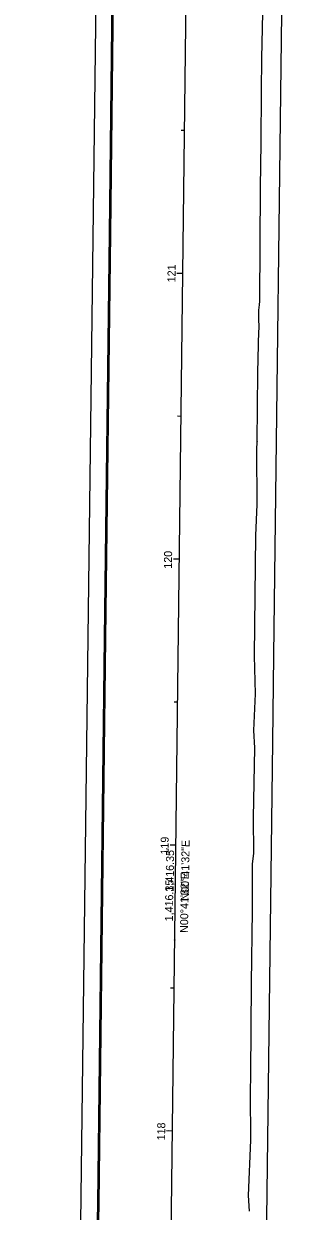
# Model space of a CAD drawing. Extents: x 1652464 to 1652601, y 605963 to 608618.
# Drawn here: x 1652507.3 to 1652601.5, y 607787.6 to 608203 of the extents above; entities that cross this region are included whole.
import ezdxf

# ---------------------------------------------------------------- set-up
doc = ezdxf.new("R2010")
doc.units = 0
for name, color, linetype in [('BD_X_Building', 7, 'Continuous'), ('BR_X_SV_Abut', 7, 'Continuous'), ('DR_X_Erosion_Control', 7, 'Continuous'), ('GE_X_Cells', 7, 'Continuous'), ('PV_X_Curb', 7, 'Continuous'), ('PV_X_Steps', 7, 'Continuous'), ('PV_X_Walk', 7, 'Continuous'), ('SV_P_Mon_Cells_Set', 7, 'Continuous'), ('SV_X_Control_Cells_Found', 7, 'Continuous'), ('SV_X_Mon_Cells_Found', 7, 'Continuous'), ('UT_X_Water_Cells', 7, 'Continuous'), ('VG_X_Cells', 7, 'Continuous'), ('VG_X_Shrub_Line_Lt', 7, 'Continuous')]:
    doc.layers.add(name, color=color, linetype=linetype)

msp = doc.modelspace()

# ---------------------------------------------------------------- linework, layer by layer
at = {"layer": 'BD_X_Building'}
msp.add_lwpolyline([(1652507.27, 606201.32), (1652514.36, 606755.06), (1652515.19, 606820.32), (1652516.55, 606927.44), (1652537.47, 608602.59)], dxfattribs=at)
at = {"layer": 'GE_X_Cells'}
for p, q in [((1652537.74, 608129.62), (1652539.44, 608285.59)), ((1652590.51, 608190.93), (1652590.92, 608212.2)), ((1652590.51, 608190.93), (1652590.92, 608212.2)), ((1652590.51, 608190.93), (1652590.92, 608212.2)), ((1652590.51, 608190.93), (1652590.92, 608212.2)), ((1652590.51, 608190.93), (1652590.92, 608212.2)), ((1652590.51, 608190.93), (1652590.92, 608212.2)), ((1652590.32, 608179.32), (1652590.51, 608190.93)), ((1652590.32, 608179.32), (1652590.51, 608190.93)), ((1652590.32, 608179.32), (1652590.51, 608190.93)), ((1652590.32, 608179.32), (1652590.51, 608190.93)), ((1652590.32, 608179.32), (1652590.51, 608190.93)), ((1652590.32, 608179.32), (1652590.51, 608190.93)), ((1652590.21, 608161.26), (1652590.32, 608179.32)), ((1652590.21, 608161.26), (1652590.32, 608179.32)), ((1652590.21, 608161.26), (1652590.32, 608179.32)), ((1652590.21, 608161.26), (1652590.32, 608179.32)), ((1652590.21, 608161.26), (1652590.32, 608179.32)), ((1652590.21, 608161.26), (1652590.32, 608179.32)), ((1652590.01, 608145.63), (1652590.21, 608161.26)), ((1652590.01, 608145.63), (1652590.21, 608161.26)), ((1652590.01, 608145.63), (1652590.21, 608161.26)), ((1652590.01, 608145.63), (1652590.21, 608161.26)), ((1652590.01, 608145.63), (1652590.21, 608161.26)), ((1652590.01, 608145.63), (1652590.21, 608161.26)), ((1652589.77, 608105.94), (1652590.01, 608145.63)), ((1652589.77, 608105.94), (1652590.01, 608145.63)), ((1652589.77, 608105.94), (1652590.01, 608145.63)), ((1652589.77, 608105.94), (1652590.01, 608145.63)), ((1652589.77, 608105.94), (1652590.01, 608145.63)), ((1652589.77, 608105.94), (1652590.01, 608145.63)), ((1652535.98, 607988.06), (1652537.74, 608129.62)), ((1652589.47, 608102.82), (1652589.65, 608104.61)), ((1652589.47, 608102.82), (1652589.65, 608104.61)), ((1652589.47, 608102.82), (1652589.65, 608104.61)), ((1652589.47, 608102.82), (1652589.65, 608104.61)), ((1652589.47, 608102.82), (1652589.65, 608104.61)), ((1652589.47, 608102.82), (1652589.65, 608104.61)), ((1652589.65, 608104.61), (1652589.77, 608105.94)), ((1652589.65, 608104.61), (1652589.77, 608105.94)), ((1652589.65, 608104.61), (1652589.77, 608105.94)), ((1652589.65, 608104.61), (1652589.77, 608105.94)), ((1652589.65, 608104.61), (1652589.77, 608105.94)), ((1652589.65, 608104.61), (1652589.77, 608105.94)), ((1652589.42, 608100.41), (1652589.47, 608102.82)), ((1652589.42, 608100.41), (1652589.47, 608102.82)), ((1652589.42, 608100.41), (1652589.47, 608102.82)), ((1652589.42, 608100.41), (1652589.47, 608102.82)), ((1652589.42, 608100.41), (1652589.47, 608102.82)), ((1652589.42, 608100.41), (1652589.47, 608102.82)), ((1652589.58, 608096.16), (1652589.42, 608100.41)), ((1652589.58, 608096.16), (1652589.42, 608100.41)), ((1652589.58, 608096.16), (1652589.42, 608100.41)), ((1652589.58, 608096.16), (1652589.42, 608100.41)), ((1652589.58, 608096.16), (1652589.42, 608100.41)), ((1652589.58, 608096.16), (1652589.42, 608100.41)), ((1652589.11, 608080.96), (1652589.49, 608095.57)), ((1652589.11, 608080.96), (1652589.49, 608095.57)), ((1652589.11, 608080.96), (1652589.49, 608095.57)), ((1652589.11, 608080.96), (1652589.49, 608095.57)), ((1652589.11, 608080.96), (1652589.49, 608095.57)), ((1652589.11, 608080.96), (1652589.49, 608095.57)), ((1652589.49, 608095.57), (1652589.58, 608096.16)), ((1652589.49, 608095.57), (1652589.58, 608096.16)), ((1652589.49, 608095.57), (1652589.58, 608096.16)), ((1652589.49, 608095.57), (1652589.58, 608096.16)), ((1652589.49, 608095.57), (1652589.58, 608096.16)), ((1652589.49, 608095.57), (1652589.58, 608096.16)), ((1652588.88, 608056.71), (1652589.11, 608080.96)), ((1652588.88, 608056.71), (1652589.11, 608080.96)), ((1652588.88, 608056.71), (1652589.11, 608080.96)), ((1652588.88, 608056.71), (1652589.11, 608080.96)), ((1652588.88, 608056.71), (1652589.11, 608080.96)), ((1652588.88, 608056.71), (1652589.11, 608080.96)), ((1652588.7, 608053.93), (1652588.9, 608056.78)), ((1652588.7, 608053.93), (1652588.9, 608056.78)), ((1652588.7, 608053.93), (1652588.9, 608056.78)), ((1652588.7, 608053.93), (1652588.9, 608056.78)), ((1652588.7, 608053.93), (1652588.9, 608056.78)), ((1652588.7, 608053.93), (1652588.9, 608056.78)), ((1652588.83, 608034.79), (1652588.7, 608053.93)), ((1652588.83, 608034.79), (1652588.7, 608053.93)), ((1652588.83, 608034.79), (1652588.7, 608053.93)), ((1652588.83, 608034.79), (1652588.7, 608053.93)), ((1652588.83, 608034.79), (1652588.7, 608053.93)), ((1652588.83, 608034.79), (1652588.7, 608053.93)), ((1652588.9, 608056.78), (1652588.88, 608056.71)), ((1652588.9, 608056.78), (1652588.88, 608056.71)), ((1652588.9, 608056.78), (1652588.88, 608056.71)), ((1652588.9, 608056.78), (1652588.88, 608056.71)), ((1652588.9, 608056.78), (1652588.88, 608056.71)), ((1652588.9, 608056.78), (1652588.88, 608056.71)), ((1652588.43, 608023.95), (1652588.83, 608034.79)), ((1652588.43, 608023.95), (1652588.83, 608034.79)), ((1652588.43, 608023.95), (1652588.83, 608034.79)), ((1652588.43, 608023.95), (1652588.83, 608034.79)), ((1652588.43, 608023.95), (1652588.83, 608034.79)), ((1652588.43, 608023.95), (1652588.83, 608034.79)), ((1652587.91, 607981.83), (1652588.43, 608023.95)), ((1652587.91, 607981.83), (1652588.43, 608023.95)), ((1652587.91, 607981.83), (1652588.43, 608023.95)), ((1652587.91, 607981.83), (1652588.43, 608023.95)), ((1652587.91, 607981.83), (1652588.43, 608023.95)), ((1652587.91, 607981.83), (1652588.43, 608023.95)), ((1652533.61, 607790.33), (1652535.98, 607988.06)), ((1652588.27, 607968.59), (1652587.91, 607981.83)), ((1652588.27, 607968.59), (1652587.91, 607981.83)), ((1652588.27, 607968.59), (1652587.91, 607981.83)), ((1652588.27, 607968.59), (1652587.91, 607981.83)), ((1652588.27, 607968.59), (1652587.91, 607981.83)), ((1652588.27, 607968.59), (1652587.91, 607981.83)), ((1652587.69, 607955.8), (1652588.27, 607968.59)), ((1652587.69, 607955.8), (1652588.27, 607968.59)), ((1652587.69, 607955.8), (1652588.27, 607968.59)), ((1652587.69, 607955.8), (1652588.27, 607968.59)), ((1652587.69, 607955.8), (1652588.27, 607968.59)), ((1652587.69, 607955.8), (1652588.27, 607968.59)), ((1652588.03, 607949.63), (1652587.69, 607955.8)), ((1652588.03, 607949.63), (1652587.69, 607955.8)), ((1652588.03, 607949.63), (1652587.69, 607955.8)), ((1652588.03, 607949.63), (1652587.69, 607955.8)), ((1652588.03, 607949.63), (1652587.69, 607955.8)), ((1652588.03, 607949.63), (1652587.69, 607955.8)), ((1652587.55, 607925.17), (1652588.03, 607949.63)), ((1652587.55, 607925.17), (1652588.03, 607949.63)), ((1652587.55, 607925.17), (1652588.03, 607949.63)), ((1652587.55, 607925.17), (1652588.03, 607949.63)), ((1652587.55, 607925.17), (1652588.03, 607949.63)), ((1652587.55, 607925.17), (1652588.03, 607949.63)), ((1652587.75, 607912.8), (1652587.55, 607925.17)), ((1652587.75, 607912.8), (1652587.55, 607925.17)), ((1652587.75, 607912.8), (1652587.55, 607925.17)), ((1652587.75, 607912.8), (1652587.55, 607925.17)), ((1652587.75, 607912.8), (1652587.55, 607925.17)), ((1652587.75, 607912.8), (1652587.55, 607925.17)), ((1652587.25, 607908.98), (1652587.75, 607912.8)), ((1652587.25, 607908.98), (1652587.75, 607912.8)), ((1652587.25, 607908.98), (1652587.75, 607912.8)), ((1652587.25, 607908.98), (1652587.75, 607912.8)), ((1652587.25, 607908.98), (1652587.75, 607912.8)), ((1652587.25, 607908.98), (1652587.75, 607912.8)), ((1652587.28, 607892.75), (1652587.25, 607908.98)), ((1652587.28, 607892.75), (1652587.25, 607908.98)), ((1652587.28, 607892.75), (1652587.25, 607908.98)), ((1652587.28, 607892.75), (1652587.25, 607908.98)), ((1652587.28, 607892.75), (1652587.25, 607908.98)), ((1652587.28, 607892.75), (1652587.25, 607908.98)), ((1652586.86, 607867.34), (1652587.28, 607892.75)), ((1652586.86, 607867.34), (1652587.28, 607892.75)), ((1652586.86, 607867.34), (1652587.28, 607892.75)), ((1652586.86, 607867.34), (1652587.28, 607892.75)), ((1652586.86, 607867.34), (1652587.28, 607892.75)), ((1652586.86, 607867.34), (1652587.28, 607892.75)), ((1652586.66, 607835.54), (1652586.86, 607867.34)), ((1652586.66, 607835.54), (1652586.86, 607867.34)), ((1652586.66, 607835.54), (1652586.86, 607867.34)), ((1652586.66, 607835.54), (1652586.86, 607867.34)), ((1652586.66, 607835.54), (1652586.86, 607867.34)), ((1652586.66, 607835.54), (1652586.86, 607867.34)), ((1652586.53, 607829.02), (1652586.66, 607835.54)), ((1652586.53, 607829.02), (1652586.66, 607835.54)), ((1652586.53, 607829.02), (1652586.66, 607835.54)), ((1652586.53, 607829.02), (1652586.66, 607835.54)), ((1652586.53, 607829.02), (1652586.66, 607835.54)), ((1652586.53, 607829.02), (1652586.66, 607835.54)), ((1652586.61, 607812.41), (1652586.53, 607829.02)), ((1652586.61, 607812.41), (1652586.53, 607829.02)), ((1652586.61, 607812.41), (1652586.53, 607829.02)), ((1652586.61, 607812.41), (1652586.53, 607829.02)), ((1652586.61, 607812.41), (1652586.53, 607829.02)), ((1652586.61, 607812.41), (1652586.53, 607829.02)), ((1652585.81, 607793.1), (1652586.61, 607812.41)), ((1652585.81, 607793.1), (1652586.61, 607812.41)), ((1652585.81, 607793.1), (1652586.61, 607812.41)), ((1652585.81, 607793.1), (1652586.61, 607812.41)), ((1652585.81, 607793.1), (1652586.61, 607812.41)), ((1652585.81, 607793.1), (1652586.61, 607812.41)), ((1652586.21, 607787.58), (1652585.81, 607793.1)), ((1652586.21, 607787.58), (1652585.81, 607793.1)), ((1652586.21, 607787.58), (1652585.81, 607793.1)), ((1652586.21, 607787.58), (1652585.81, 607793.1)), ((1652586.21, 607787.58), (1652585.81, 607793.1)), ((1652586.21, 607787.58), (1652585.81, 607793.1)), ((1652531.98, 607668.47), (1652533.61, 607790.33))]:
    msp.add_line(p, q, dxfattribs=at)
at = {"layer": 'PV_X_Curb'}
msp.add_line((1652551.76, 607199.34), (1652568.87, 608615.58), dxfattribs=at)
at = {"layer": 'PV_X_Steps'}
msp.add_lwpolyline([(1652570.42, 606048.23), (1652570.59, 606069.16), (1652572.96, 606254.92), (1652575.24, 606433.07), (1652576.4, 606523.06), (1652578.06, 606652.96), (1652579.12, 606736.34), (1652580.12, 606814.04), (1652581.65, 606935.48), (1652585.26, 607224.58), (1652586.28, 607305.92), (1652588.75, 607503.82), (1652591.34, 607710.88), (1652594.35, 607951.77), (1652594.72, 607981.92), (1652597.89, 608234.94), (1652601.47, 608521.97)], dxfattribs=at)
at = {"layer": 'PV_X_Walk'}
for p, q in [((1652537.24, 608129.62), (1652538.94, 608285.59)), ((1652537.24, 608129.62), (1652538.94, 608285.59)), ((1652535.48, 607988.07), (1652537.24, 608129.62)), ((1652535.48, 607988.07), (1652537.24, 608129.62)), ((1652533.11, 607790.34), (1652535.48, 607988.07)), ((1652533.11, 607790.34), (1652535.48, 607988.07)), ((1652531.48, 607668.47), (1652533.11, 607790.34)), ((1652531.48, 607668.47), (1652533.11, 607790.34))]:
    msp.add_line(p, q, dxfattribs=at)
at = {"layer": 'SV_X_Control_Cells_Found'}
msp.add_line((1652551.76, 607199.34), (1652568.87, 608615.58), dxfattribs=at)
msp.add_line((1652551.76, 607199.34), (1652568.87, 608615.58), dxfattribs=at)
at = {"layer": 'SV_X_Mon_Cells_Found'}
msp.add_circle((1652560.02, 607882.46), 0.05, dxfattribs=at)
msp.add_circle((1652560.02, 607882.46), 0.05, dxfattribs=at)
msp.add_circle((1652560.02, 607882.46), 0.05, dxfattribs=at)
msp.add_circle((1652560.02, 607882.46), 0.05, dxfattribs=at)
at = {"layer": 'VG_X_Cells'}
for p, q in [((1652563.44, 608165.61), (1652562.24, 608165.63)), ((1652562.83, 608115.62), (1652560.83, 608115.64)), ((1652562.23, 608065.62), (1652561.03, 608065.64)), ((1652561.62, 608015.63), (1652559.62, 608015.65)), ((1652561.02, 607965.63), (1652559.82, 607965.64)), ((1652560.42, 607915.63), (1652558.42, 607915.66)), ((1652559.81, 607865.64), (1652558.61, 607865.65)), ((1652559.21, 607815.64), (1652557.21, 607815.66))]:
    msp.add_line(p, q, dxfattribs=at)
at = {"layer": 'VG_X_Shrub_Line_Lt'}
for p, q in [((1652562.83, 608115.62), (1652561.63, 608115.63)), ((1652561.62, 608015.63), (1652559.62, 608015.65)), ((1652560.42, 607915.63), (1652559.22, 607915.65)), ((1652559.21, 607815.64), (1652558.01, 607815.65))]:
    msp.add_line(p, q, dxfattribs=at)

# ---------------------------------------------------------------- texts
at = {"layer": 'BR_X_SV_Abut'}
msp.add_text('N00°41\'32"E', height=2.8, rotation=89.3076, dxfattribs=at).set_placement((1652564.98, 607896.22))
at = {"layer": 'DR_X_Erosion_Control'}
msp.add_text("1,416.35'", height=2.8, rotation=89.3076, dxfattribs=at).set_placement((1652559.66, 607899.35))
at = {"layer": 'SV_P_Mon_Cells_Set'}
msp.add_text('N00°41\'32"E', height=2.8, rotation=89.3076, dxfattribs=at).set_placement((1652564.7, 607884.92))
at = {"layer": 'UT_X_Water_Cells'}
msp.add_text("1,416.35'", height=2.8, rotation=89.3076, dxfattribs=at).set_placement((1652559.4, 607888.97))
at = {"layer": 'VG_X_Cells'}
for s, p in [('121', (1652560.29, 608112.5)), ('120', (1652559.08, 608012.31)), ('119', (1652557.88, 607912.34)), ('118', (1652556.67, 607812.34))]:
    msp.add_text(s, height=2.8, rotation=89.3076, dxfattribs=at).set_placement(p)
at = {"layer": 'VG_X_Shrub_Line_Lt'}
msp.add_text('120', height=2.8, rotation=89.3076, dxfattribs=at).set_placement((1652559.04, 608012.31))

doc.saveas('drawing.dxf')
